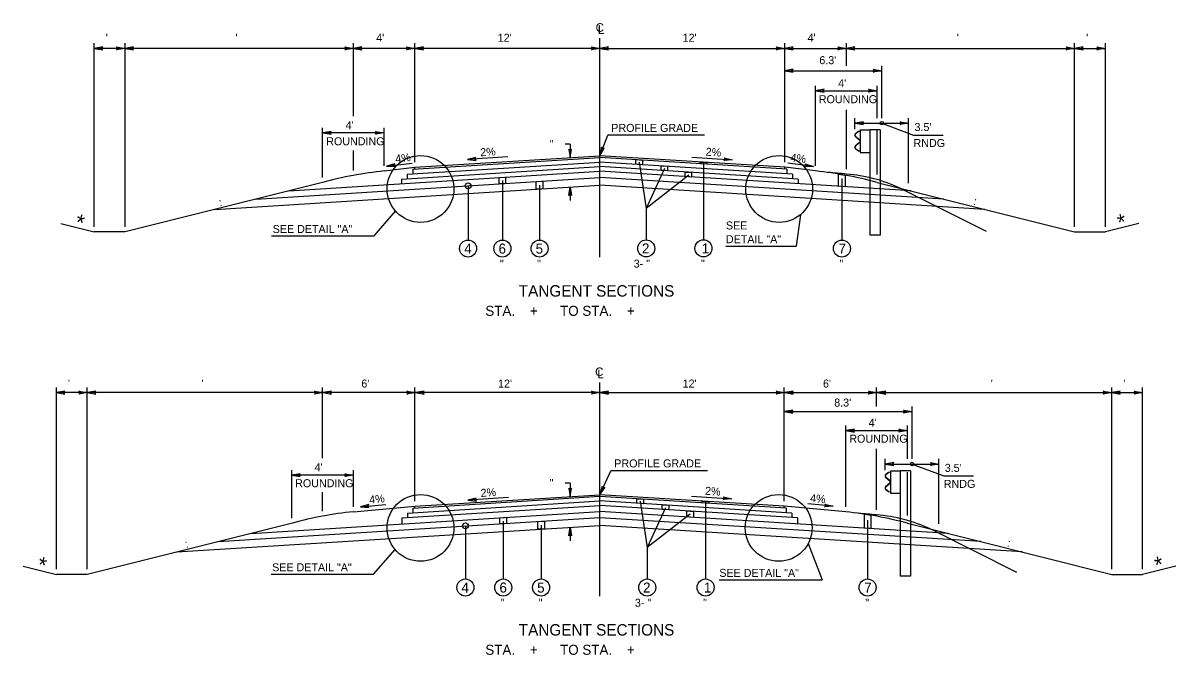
# Model space of a CAD drawing. Extents: x -540 to 1231, y -564 to 421.
# Drawn here: x 182.7 to 384.3, y -192.9 to -82.5 of the extents above; entities that cross this region are included whole.
import ezdxf

# ---------------------------------------------------------------- set-up
doc = ezdxf.new("R2010")
doc.units = 0
doc.layers.add('1', color=7, linetype='Continuous')
doc.layers.add('Des_ Drain_ Ftrs', color=7, linetype='Continuous')

msp = doc.modelspace()

# ---------------------------------------------------------------- linework, layer by layer
at = {"layer": '1'}
for p, q in [((195.16, -118.1), (195.16, -86.03)), ((200.55, -118.1), (200.55, -86.03)), ((240.47, -98.78), (240.47, -86.03)), ((251.25, -106.83), (251.25, -86.03)), ((283.58, -123.4), (283.58, -85.15)), ((315.91, -106.83), (315.91, -86.03)), ((326.68, -89.98), (326.68, -86.03)), ((366.6, -118.1), (366.6, -86.03)), ((371.99, -118.1), (371.99, -86.03)), ((200.55, -86.91), (195.16, -86.91)), ((240.47, -86.91), (200.55, -86.91)), ((251.25, -86.91), (240.47, -86.91)), ((283.58, -86.91), (251.25, -86.91)), ((283.58, -86.91), (315.91, -86.91)), ((315.91, -86.91), (326.68, -86.91)), ((326.68, -86.91), (366.6, -86.91)), ((366.6, -86.91), (371.99, -86.91)), ((332.88, -99.11), (332.88, -89.95)), ((315.91, -90.83), (332.88, -90.83)), ((321.3, -107.46), (321.3, -93.44)), ((321.3, -94.32), (332.07, -94.32)), ((332.07, -99.11), (332.07, -93.44)), ((326.68, -108.02), (326.68, -97.65)), ((235.08, -109.47), (235.08, -100.8)), ((245.86, -107.46), (245.86, -100.8)), ((328.19, -101.06), (328.19, -99.11)), ((328.19, -99.99), (337.57, -99.99)), ((332.88, -99.99), (338.44, -102.06)), ((337.57, -110.47), (337.57, -99.11)), ((245.86, -101.68), (235.08, -101.68)), ((283.58, -105.68), (284.95, -102.11)), ((301.87, -102.11), (284.95, -102.11)), ((328.25, -102.28), (328.99, -102.91)), ((328.79, -101.46), (328.27, -101.85)), ((328.27, -102.26), (329, -102.89)), ((328.8, -101.48), (328.29, -101.87)), ((329.1, -101.4), (328.79, -101.46)), ((329.1, -101.43), (328.8, -101.48)), ((329.1, -101.17), (329.1, -105.1)), ((329.1, -101.17), (330.79, -101.17)), ((330.79, -101.17), (330.79, -119.57)), ((332.61, -101.17), (330.79, -101.17)), ((332.07, -108.99), (332.07, -101.09)), ((332.61, -101.17), (332.61, -119.57)), ((338.44, -102.06), (343.59, -102.06)), ((240.47, -108.24), (240.47, -104.74)), ((278.4, -103.64), (277.52, -103.64)), ((278.4, -103.64), (278.4, -106)), ((328.99, -103.36), (328.25, -104)), ((329, -103.39), (328.27, -104.02)), ((328.27, -104.43), (328.79, -104.82)), ((328.29, -104.41), (328.8, -104.79)), ((328.79, -104.82), (329.1, -104.88)), ((328.8, -104.79), (329.1, -104.85)), ((329.07, -103.1), (329.07, -103.18)), ((329.1, -103.1), (329.1, -103.18)), ((249.9, -108.9), (283.58, -106.79)), ((250.88, -108.03), (283.58, -105.98)), ((251.25, -107.71), (283.58, -105.68)), ((267.51, -105.9), (260.43, -106.35)), ((315.91, -107.71), (283.58, -105.68)), ((316.27, -108.03), (283.58, -105.98)), ((317.26, -108.9), (283.58, -106.79)), ((290.44, -106.81), (291.68, -114.93)), ((299.68, -105.93), (306.76, -106.38)), ((329.1, -105.1), (330.79, -105.1)), ((229.2, -111.82), (283.58, -108.4)), ((245.86, -108.34), (251.25, -107.71)), ((246.29, -107.51), (250.76, -106.98)), ((248.91, -109.77), (283.58, -107.59)), ((250.88, -108.03), (250.88, -108.84)), ((251.25, -108.01), (251.25, -107.71)), ((318.25, -109.77), (283.58, -107.59)), ((337.95, -111.82), (283.58, -108.4)), ((294.87, -107.91), (291.68, -114.93)), ((301.69, -106.97), (301.69, -120.39)), ((315.91, -108.01), (315.91, -107.71)), ((321.3, -108.34), (315.91, -107.71)), ((316.27, -108.03), (316.27, -108.84)), ((320.93, -107.54), (316.46, -107.01)), ((235.08, -110.35), (200.55, -118.98)), ((216.23, -115.06), (283.58, -110.83)), ((223.44, -113.26), (283.58, -109.48)), ((248.91, -109.77), (248.91, -110.58)), ((249.9, -108.9), (249.9, -109.71)), ((266.53, -110.01), (266.53, -120.43)), ((273.03, -110.82), (273.03, -120.43)), ((343.72, -113.26), (283.58, -109.48)), ((350.92, -115.06), (283.58, -110.83)), ((299.14, -109.1), (291.68, -114.93)), ((317.26, -108.9), (317.26, -109.71)), ((318.25, -109.77), (318.25, -110.58)), ((325.91, -109.64), (325.91, -120.43)), ((328.19, -109.12), (328.19, -109.12)), ((332.07, -110.35), (366.6, -118.98)), ((260.53, -110.94), (260.53, -120.43)), ((278.4, -111.16), (278.4, -113.52)), ((336.07, -111.35), (351.12, -118.88)), ((244.11, -119.69), (247.85, -115.37)), ((291.68, -114.93), (291.68, -120.4)), ((318.64, -116.01), (317.92, -121.47)), ((189.33, -117.53), (195.16, -118.98)), ((377.82, -117.53), (371.99, -118.98)), ((200.55, -118.98), (195.16, -118.98)), ((226.18, -119.69), (244.11, -119.69)), ((332.61, -119.57), (330.79, -119.57)), ((366.6, -118.98), (371.99, -118.98)), ((305.61, -121.47), (317.92, -121.47)), ((188.54, -177.98), (188.54, -146.21)), ((193.93, -147.09), (188.54, -147.09)), ((193.93, -177.98), (193.93, -146.21)), ((235.17, -147.09), (193.93, -147.09)), ((235.08, -158.55), (235.08, -146.21)), ((251.34, -147.09), (235.17, -147.09)), ((251.25, -166.08), (251.25, -146.21)), ((283.58, -147.09), (251.34, -147.09)), ((283.58, -182.65), (283.58, -145.33)), ((283.58, -147.09), (315.91, -147.09)), ((315.82, -166.08), (315.82, -146.21)), ((315.91, -147.09), (332.07, -147.09)), ((331.98, -149.53), (331.98, -146.21)), ((332.07, -147.09), (373.1, -147.09)), ((373.1, -177.98), (373.1, -146.21)), ((373.1, -147.09), (378.49, -147.09)), ((378.49, -177.98), (378.49, -146.21)), ((315.82, -150.41), (338.18, -150.41)), ((338.18, -158.69), (338.18, -149.53)), ((326.59, -167.04), (326.59, -152.86)), ((337.37, -158.69), (337.37, -152.86)), ((326.59, -153.74), (337.36, -153.74)), ((331.98, -167.6), (331.98, -156.91)), ((333.49, -160.64), (333.49, -158.69)), ((342.87, -170.03), (342.87, -158.69)), ((229.7, -169.04), (229.7, -160.65)), ((240.47, -167.04), (240.47, -160.65)), ((283.58, -164.94), (285.49, -160.74)), ((302.4, -160.74), (285.49, -160.74)), ((333.49, -159.57), (342.87, -159.57)), ((334.08, -161.04), (333.57, -161.43)), ((334.1, -161.06), (333.58, -161.45)), ((334.4, -160.98), (334.08, -161.04)), ((334.4, -161.01), (334.1, -161.06)), ((334.4, -160.75), (334.4, -164.68)), ((334.4, -160.75), (336.08, -160.75)), ((336.08, -160.75), (336.08, -179.15)), ((337.91, -160.75), (336.08, -160.75)), ((337.37, -168.57), (337.37, -161)), ((337.91, -160.75), (337.91, -179.15)), ((338.18, -159.57), (343.73, -161.64)), ((240.47, -161.53), (229.7, -161.53)), ((278.38, -162.89), (277.5, -162.89)), ((278.38, -162.89), (278.38, -165.26)), ((333.55, -161.86), (334.28, -162.49)), ((334.28, -162.94), (333.55, -163.58)), ((333.57, -161.84), (334.3, -162.47)), ((334.3, -162.97), (333.57, -163.6)), ((334.37, -162.68), (334.37, -162.76)), ((334.4, -162.68), (334.4, -162.76)), ((343.73, -161.64), (348.89, -161.64)), ((235.08, -167.81), (235.08, -164.48)), ((250.89, -167.28), (283.58, -165.22)), ((251.25, -166.96), (283.58, -164.93)), ((315.82, -166.96), (283.58, -164.94)), ((316.18, -167.28), (283.58, -165.23)), ((299.58, -165.2), (306.65, -165.65)), ((333.57, -164.01), (334.08, -164.4)), ((333.58, -163.99), (334.1, -164.37)), ((334.08, -164.4), (334.4, -164.46)), ((334.1, -164.37), (334.4, -164.43)), ((334.4, -164.68), (336.08, -164.68)), ((240.47, -167.91), (251.25, -166.96)), ((241.7, -167.04), (246.18, -166.64)), ((248.93, -168.99), (283.58, -166.82)), ((249.92, -168.14), (283.58, -166.02)), ((250.89, -167.28), (250.89, -168.07)), ((251.25, -167.26), (251.25, -166.96)), ((267.58, -165.44), (260.5, -165.89)), ((317.16, -168.14), (283.58, -166.03)), ((318.13, -169), (283.58, -166.83)), ((290.64, -166.09), (291.87, -174.19)), ((295.04, -167.21), (291.87, -174.19)), ((302.07, -166.24), (302.07, -179.68)), ((315.82, -167.26), (315.82, -166.96)), ((326.59, -167.92), (315.82, -166.96)), ((316.18, -167.28), (316.18, -168.08)), ((324.4, -166.95), (319.92, -166.55)), ((216.85, -173.13), (283.58, -168.94)), ((222.57, -171.7), (283.58, -167.87)), ((248.94, -168.99), (248.94, -170.05)), ((249.92, -168.14), (249.92, -168.93)), ((344.47, -171.71), (283.58, -167.88)), ((350.19, -173.14), (283.58, -168.95)), ((299.38, -168.31), (291.87, -174.19)), ((317.16, -168.14), (317.16, -168.94)), ((318.13, -169), (318.13, -170.05)), ((333.49, -168.7), (333.49, -168.7)), ((229.82, -169.89), (193.93, -178.86)), ((209.61, -174.94), (283.58, -170.29)), ((260.06, -170.38), (260.06, -179.68)), ((266.69, -169.55), (266.69, -179.68)), ((273.3, -170.28), (273.3, -179.68)), ((278.37, -170.62), (278.37, -172.99)), ((357.43, -174.95), (283.58, -170.3)), ((330.4, -169.36), (330.4, -179.68)), ((337.37, -169.93), (373.1, -178.86)), ((341.37, -170.93), (356.42, -178.46)), ((244.02, -178.83), (247.76, -174.51)), ((291.87, -174.19), (291.87, -179.68)), ((320.02, -173.47), (322.46, -179.81)), ((182.71, -177.41), (188.54, -178.86)), ((384.32, -177.41), (378.49, -178.86)), ((193.93, -178.86), (188.54, -178.86)), ((226.09, -178.83), (244.02, -178.83)), ((337.91, -179.15), (336.08, -179.15)), ((373.1, -178.86), (378.49, -178.86)), ((304.46, -179.81), (322.46, -179.81))]:
    msp.add_line(p, q, dxfattribs=at)
for points in [[(289.87, -106.37), (291.02, -106.44), (291.02, -107.25), (289.87, -107.18)], [(301.11, -106.78), (302.26, -106.85), (302.26, -107.15), (301.11, -107.08)], [(294.27, -107.46), (295.42, -107.53), (295.42, -108.34), (294.27, -108.27)], [(298.47, -108.53), (299.61, -108.6), (299.61, -109.41), (298.47, -109.34)], [(265.95, -109.51), (267.1, -109.44), (267.1, -110.52), (265.95, -110.59)], [(272.45, -110.18), (273.6, -110.11), (273.6, -111.46), (272.45, -111.53)], [(325.33, -108.88), (326.48, -109.08), (326.48, -111.1), (325.33, -111.03)], [(290.06, -165.64), (291.21, -165.71), (291.21, -166.51), (290.06, -166.44)], [(294.47, -166.71), (295.62, -166.79), (295.62, -167.58), (294.47, -167.51)], [(301.49, -166.06), (302.64, -166.14), (302.64, -166.43), (301.49, -166.36)], [(266.11, -168.97), (267.26, -168.89), (267.26, -169.97), (266.11, -170.04)], [(298.81, -167.78), (299.96, -167.86), (299.96, -168.91), (298.81, -168.83)], [(329.83, -168.34), (330.97, -168.52), (330.97, -170.86), (329.83, -170.79)], [(272.73, -169.62), (273.87, -169.55), (273.87, -170.9), (272.73, -170.98)]]:
    msp.add_lwpolyline(points, close=True, dxfattribs=at)
for centre, radius in [((332.88, -99.99), 0.3), ((252.21, -111.49), 5.84), ((314.94, -111.49), 5.84), ((260.53, -110.94), 0.5), ((260.53, -121.91), 1.49), ((266.53, -121.91), 1.49), ((273.03, -121.91), 1.49), ((291.68, -121.88), 1.49), ((301.69, -121.87), 1.49), ((325.91, -121.91), 1.49), ((338.18, -159.57), 0.3), ((252.21, -170.74), 5.84), ((314.85, -170.74), 5.84), ((260.06, -170.38), 0.5), ((260.06, -181.16), 1.49), ((266.69, -181.16), 1.49), ((273.3, -181.16), 1.49), ((291.87, -181.16), 1.49), ((302.07, -181.16), 1.49), ((330.4, -181.16), 1.49)]:
    msp.add_circle(centre, radius, dxfattribs=at)
for centre, radius, start, end in [((328.44, -102.07), 0.278, 126.9799, 229.021), ((328.44, -102.07), 0.249, 126.9799, 229.021), ((328.44, -104.21), 0.278, 130.979, 233.0201), ((328.44, -104.21), 0.249, 130.979, 233.0201), ((328.82, -103.1), 0.249, 0, 49.0365), ((328.82, -103.18), 0.249, 310.9635, 0), ((328.82, -103.1), 0.278, 0, 49.0365), ((328.82, -103.18), 0.278, 310.9635, 0), ((252.74, -175.18), 67.19, 95.8795, 105.2381), ((314.41, -175.18), 67.19, 74.7593, 84.1179), ((315.87, -209.56), 101.24, 83.8633, 85.6775), ((324.57, -136.18), 27.37, 65.1374, 85.5513), ((333.73, -161.65), 0.278, 126.9799, 229.021), ((333.73, -161.65), 0.249, 126.9799, 229.021), ((334.12, -162.68), 0.249, 0, 49.0365), ((334.12, -162.76), 0.249, 310.9635, 0), ((334.12, -162.68), 0.278, 0, 49.0365), ((334.12, -162.76), 0.278, 310.9635, 0), ((333.73, -163.79), 0.278, 130.979, 233.0201), ((333.73, -163.79), 0.249, 130.979, 233.0201), ((247.35, -234.75), 67.19, 95.8795, 105.1262), ((319.71, -234.76), 67.19, 74.7611, 84.1196), ((321.16, -269.14), 101.24, 83.8633, 85.6775), ((329.86, -195.76), 27.37, 65.1374, 85.5513)]:
    msp.add_arc(centre, radius, start, end, dxfattribs=at)
at = {"layer": 'Des_ Drain_ Ftrs'}
for points in [[(195.16, -86.91), (196.65, -87.16), (196.35, -86.91), (196.65, -86.67)], [(200.55, -86.91), (199.06, -87.16), (199.36, -86.91), (199.06, -86.67)], [(200.55, -86.91), (202.04, -87.16), (201.74, -86.91), (202.04, -86.67)], [(240.47, -86.91), (238.98, -87.16), (239.28, -86.91), (238.98, -86.67)], [(240.47, -86.91), (241.96, -87.16), (241.67, -86.91), (241.96, -86.67)], [(251.25, -86.91), (249.76, -87.16), (250.06, -86.91), (249.76, -86.67)], [(251.25, -86.91), (252.74, -87.16), (252.44, -86.91), (252.74, -86.67)], [(283.58, -86.91), (282.09, -87.16), (282.38, -86.91), (282.09, -86.67)], [(283.58, -86.91), (285.07, -87.16), (284.77, -86.91), (285.07, -86.67)], [(315.91, -86.91), (314.42, -87.16), (314.71, -86.91), (314.42, -86.67)], [(315.91, -86.91), (317.4, -87.16), (317.1, -86.91), (317.4, -86.67)], [(326.68, -86.91), (325.2, -87.16), (325.49, -86.91), (325.2, -86.67)], [(326.68, -86.91), (328.17, -87.16), (327.88, -86.91), (328.17, -86.67)], [(366.6, -86.91), (365.11, -87.16), (365.41, -86.91), (365.11, -86.67)], [(366.6, -86.91), (368.09, -87.16), (367.8, -86.91), (368.09, -86.67)], [(371.99, -86.91), (370.5, -87.16), (370.8, -86.91), (370.5, -86.67)], [(315.91, -90.83), (317.4, -91.08), (317.1, -90.83), (317.4, -90.58)], [(332.88, -90.83), (331.39, -91.08), (331.69, -90.83), (331.39, -90.58)], [(321.3, -94.32), (322.78, -94.57), (322.49, -94.32), (322.78, -94.07)], [(332.07, -94.32), (330.58, -94.57), (330.88, -94.32), (330.58, -94.07)], [(328.19, -99.99), (329.68, -100.24), (329.38, -99.99), (329.68, -99.74)], [(337.57, -99.99), (336.08, -100.24), (336.38, -99.99), (336.08, -99.74)], [(235.08, -101.68), (236.57, -101.92), (236.28, -101.68), (236.57, -101.43)], [(245.86, -101.68), (244.37, -101.92), (244.67, -101.68), (244.37, -101.43)], [(278.4, -106), (278.64, -104.52), (278.4, -104.81), (278.15, -104.52)], [(283.58, -105.68), (284.34, -104.38), (284, -104.56), (283.88, -104.2)], [(260.43, -106.35), (261.93, -106.5), (261.62, -106.27), (261.9, -106.01)], [(306.76, -106.38), (305.26, -106.53), (305.57, -106.3), (305.29, -106.04)], [(246.29, -107.51), (247.8, -107.58), (247.48, -107.37), (247.74, -107.09)], [(320.93, -107.54), (319.42, -107.61), (319.74, -107.4), (319.48, -107.12)], [(278.4, -111.16), (278.64, -112.64), (278.4, -112.35), (278.15, -112.64)], [(188.54, -147.09), (190.03, -147.34), (189.73, -147.09), (190.03, -146.85)], [(193.93, -147.09), (192.44, -147.34), (192.74, -147.09), (192.44, -146.85)], [(193.93, -147.09), (195.42, -147.34), (195.12, -147.09), (195.42, -146.85)], [(235.17, -147.09), (233.69, -147.34), (233.98, -147.09), (233.69, -146.85)], [(235.17, -147.09), (236.66, -147.34), (236.37, -147.09), (236.66, -146.85)], [(251.34, -147.09), (249.85, -147.34), (250.15, -147.09), (249.85, -146.85)], [(251.34, -147.09), (252.83, -147.34), (252.53, -147.09), (252.83, -146.85)], [(283.58, -147.09), (282.09, -147.34), (282.39, -147.09), (282.09, -146.85)], [(283.58, -147.09), (285.07, -147.34), (284.77, -147.09), (285.07, -146.85)], [(315.91, -147.09), (314.42, -147.34), (314.71, -147.09), (314.42, -146.85)], [(315.91, -147.09), (317.4, -147.34), (317.1, -147.09), (317.4, -146.85)], [(332.07, -147.09), (330.58, -147.34), (330.88, -147.09), (330.58, -146.85)], [(332.07, -147.09), (333.56, -147.34), (333.27, -147.09), (333.56, -146.85)], [(373.1, -147.09), (371.61, -147.34), (371.91, -147.09), (371.61, -146.85)], [(373.1, -147.09), (374.59, -147.34), (374.29, -147.09), (374.59, -146.85)], [(378.49, -147.09), (377, -147.34), (377.3, -147.09), (377, -146.85)], [(315.82, -150.41), (317.3, -150.66), (317.01, -150.41), (317.3, -150.16)], [(338.18, -150.41), (336.69, -150.66), (336.98, -150.41), (336.69, -150.16)], [(326.59, -153.74), (328.08, -153.99), (327.78, -153.74), (328.08, -153.49)], [(337.36, -153.74), (335.88, -153.99), (336.17, -153.74), (335.88, -153.49)], [(333.49, -159.57), (334.97, -159.82), (334.68, -159.57), (334.97, -159.32)], [(342.87, -159.57), (341.38, -159.82), (341.68, -159.57), (341.38, -159.32)], [(229.7, -161.53), (231.18, -161.78), (230.89, -161.53), (231.18, -161.29)], [(240.47, -161.53), (238.98, -161.78), (239.28, -161.53), (238.98, -161.29)], [(278.38, -165.26), (278.62, -163.77), (278.38, -164.06), (278.13, -163.77)], [(283.58, -164.94), (284.42, -163.68), (284.07, -163.85), (283.97, -163.48)], [(306.65, -165.65), (305.15, -165.8), (305.46, -165.58), (305.18, -165.31)], [(241.7, -167.04), (243.2, -167.15), (242.88, -166.93), (243.16, -166.66)], [(260.5, -165.89), (262, -166.04), (261.69, -165.81), (261.97, -165.54)], [(324.4, -166.95), (322.89, -167.07), (323.21, -166.85), (322.94, -166.57)], [(278.37, -170.62), (278.62, -172.11), (278.37, -171.81), (278.13, -172.11)]]:
    msp.add_lwpolyline(points, close=True, dxfattribs=at)

# ---------------------------------------------------------------- texts
at = {"layer": '1'}
for s, height, p in [(" '", 1.4, (196.66, -85.76)), ("  '", 1.4, (218.81, -85.76)), ("4'", 1.4, (244.47, -85.76)), ("12'", 1.4, (265.72, -85.76)), ("12'", 1.4, (298.05, -85.76)), ("4'", 1.4, (319.9, -85.76)), ("  '", 1.4, (344.95, -85.76)), (" '", 1.4, (368.1, -85.76)), ("6.3'", 1.4, (321.96, -89.68)), ("4'", 1.4, (325.26, -93.7)), ('ROUNDING', 1.4, (321.87, -96.5)), ("4'", 1.4, (239.12, -101.06)), ('PROFILE GRADE', 1.4, (285.57, -101.52)), ("3.5'", 1.4, (338.6, -101.36)), ('ROUNDING', 1.4, (235.73, -103.86)), ('RNDG', 1.4, (338.43, -104.16)), ('SEE DETAIL "A"', 1.4, (226.37, -119.19)), ('SEE', 1.4, (305.62, -118.57)), ('DETAIL "A"', 1.4, (305.62, -120.97)), ('4', 1.75, (259.86, -122.79)), ('6', 1.75, (265.86, -122.79)), ('5', 1.75, (272.34, -122.79)), ('2', 1.75, (290.94, -122.76)), ('1', 1.75, (301.39, -122.75)), ('7', 1.75, (325.31, -122.79)), (' "', 1.4, (265.58, -125.27)), (' "', 1.4, (272.08, -125.27)), ('3- "', 1.4, (289.5, -125.24)), (' "', 1.4, (300.74, -125.23)), (' "', 1.4, (324.96, -125.27)), ('TANGENT SECTIONS', 2, (269.4, -130.31)), ('STA.    +      TO STA.    +     ', 1.75, (263.55, -133.67)), (" '", 1.4, (190.04, -146.21)), ("  '", 1.4, (212.86, -146.21)), ("6'", 1.4, (241.87, -146.21)), ("12'", 1.4, (265.77, -146.21)), ("12'", 1.4, (298.05, -146.21)), ("6'", 1.4, (322.6, -146.21)), ("  '", 1.4, (350.89, -146.21)), (" '", 1.4, (374.6, -146.21)), ("8.3'", 1.4, (324.56, -149.53)), ("4'", 1.4, (330.59, -153.04)), ('ROUNDING', 1.4, (327.2, -155.84)), ('PROFILE GRADE', 1.4, (286.1, -160.16)), ("4'", 1.4, (233.69, -160.83)), ("3.5'", 1.4, (343.89, -160.94)), ('ROUNDING', 1.4, (230.3, -163.63)), ('RNDG', 1.4, (343.72, -163.74)), ('SEE DETAIL "A"', 1.4, (226.27, -178.33)), ('SEE DETAIL "A"', 1.4, (304.47, -179.3)), ('4', 1.75, (259.38, -182.04)), ('6', 1.75, (266.02, -182.04)), ('5', 1.75, (272.61, -182.04)), ('2', 1.75, (291.13, -182.04)), ('1', 1.75, (301.77, -182.04)), ('7', 1.75, (329.81, -182.04)), (' "', 1.4, (265.74, -184.52)), (' "', 1.4, (272.36, -184.52)), ('3- "', 1.4, (289.7, -184.52)), (' "', 1.4, (301.12, -184.52)), ('  "', 1.4, (328.96, -184.52)), ('TANGENT SECTIONS', 2, (269.4, -189.56)), ('STA.    +      TO STA.    +     ', 1.75, (263.55, -192.92))]:
    msp.add_text(s, height=height, dxfattribs=at).set_placement(p)
for s, height, rotation, p in [('2%', 1.4, 3.7204, (262.7, -105.79)), ('  "', 1.4, 0.1438, (273.78, -104.34)), ('2%', 1.4, 356.2798, (302.05, -105.66)), ('4%', 1.4, 6.9824, (247.89, -106.93)), ('4%', 1.4, 353.0228, (316.84, -106.66)), (' : ', 1.4, 14.2282, (216.63, -114.68)), (' : ', 1.4, 345.7718, (348.29, -114.12)), ('*', 2.8, 347.1521, (191.65, -118.55)), ('*', 2.8, 12.8479, (374.45, -118.79)), ('  "', 1.4, 0.1438, (273.76, -163.59)), ('4%', 1.4, 5.3488, (243.31, -166.51)), ('2%', 1.4, 3.7232, (262.77, -165.33)), ('2%', 1.4, 356.2768, (301.94, -164.93)), ('4%', 1.4, 354.6118, (320.29, -166.19)), (' : ', 1.4, 14.2282, (210.7, -174.39)), (' : ', 1.4, 345.7718, (354.19, -173.85)), ('*', 2.8, 347.1521, (185.03, -178.43)), ('*', 2.8, 12.8479, (380.95, -178.67))]:
    msp.add_text(s, height=height, rotation=rotation, dxfattribs=at).set_placement(p)
at = {"layer": 'Des_ Drain_ Ftrs'}
for s, p in [('C', (282.84, -84.02)), ('L', (283.23, -84.41)), ('C', (282.75, -144.2)), ('L', (283.15, -144.6))]:
    msp.add_text(s, height=1.5, dxfattribs=at).set_placement(p)

doc.saveas('drawing.dxf')
